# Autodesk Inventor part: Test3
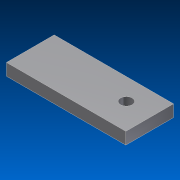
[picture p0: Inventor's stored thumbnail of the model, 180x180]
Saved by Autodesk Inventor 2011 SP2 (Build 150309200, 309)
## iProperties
Created: 2012-03
Part Number: Test3
Document SubType Name: Modeling
Designer: BH
Density: 1 g/cm^3
Author: BH
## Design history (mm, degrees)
sketch "Skizze1"
  geometry: L1 (0, 0)-(100, 0); L2 (100, 0)-(100, -40); L3 (100, -40)-(0, -40); L4 (0, -40)-(0, 0)
  constraints: 8 end point, 2 parallel, 1 horizontal, 1 perpendicular
  dimensions: "d0" = 100 distance of L2.end L3.end; "d1" = 40 distance of L1.end L2.end
extrude "Extrusion1" new body sketch "Skizze1" distance "d2" = 10; taper "d3" = 0 deg
sketch "Skizze2"
  geometry: C1 r 4.883 at (78.482, -17.999)
  constraints: 1 centre point
extrude "Extrusion2" cut sketch "Skizze2" distance "d4" = 10; taper "d5" = 0 deg
node "Volumenkörper1"
